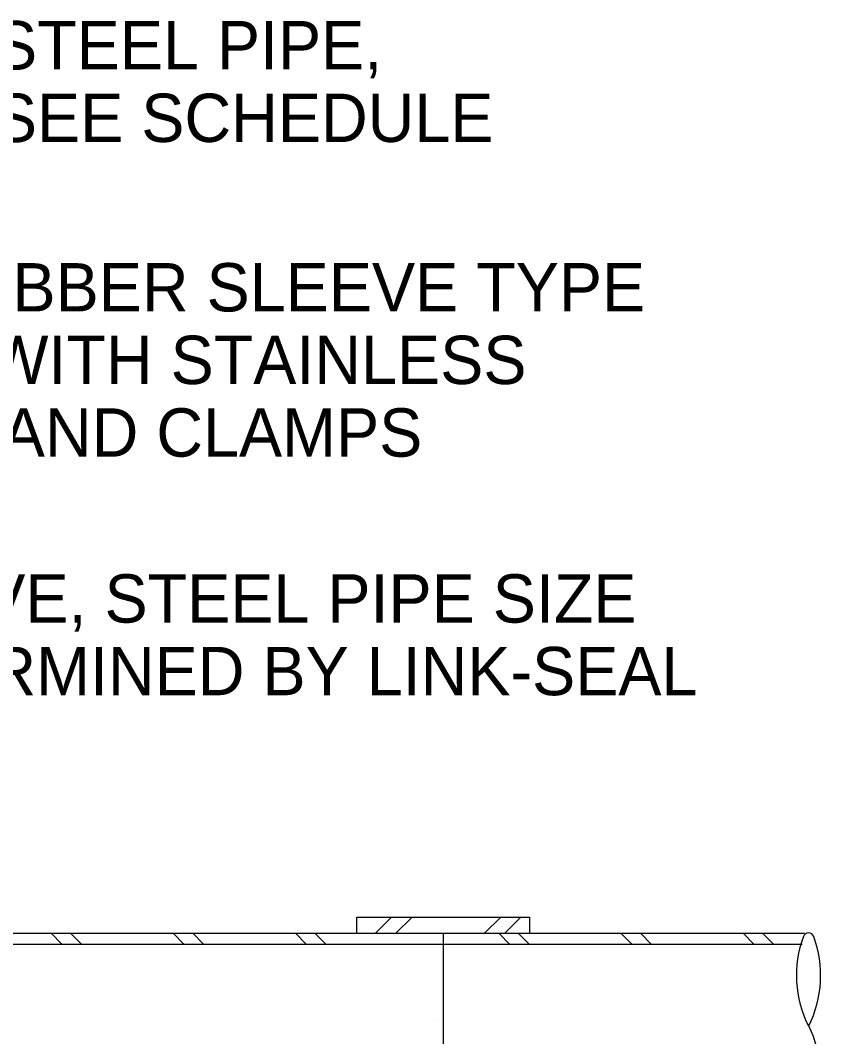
# Model space of a CAD drawing. Extents: x 22422.9 to 22498.9, y 22369.6 to 22415.
# Drawn here: x 22434.748 to 22437.837, y 22392.447 to 22396.373 of the extents above; entities that cross this region are included whole.
import ezdxf

# ---------------------------------------------------------------- set-up
doc = ezdxf.new("R2010")
doc.units = 0
for name, color, linetype in [('Level 1', 7, 'Continuous'), ('Level 2', 7, 'Continuous'), ('Level 4', 7, 'Continuous'), ('Level 8', 7, 'Continuous')]:
    doc.layers.add(name, color=color, linetype=linetype)

msp = doc.modelspace()

# ---------------------------------------------------------------- linework, layer by layer
at = {"layer": 'Level 1'}
for p, q in [((22436.3804, 22392.5676), (22436.3804, 22392.5676)), ((22436.3443, 22392.5084), (22436.3443, 22392.5084))]:
    msp.add_line(p, q, dxfattribs=at)
for centre, radius, start, end in [((22437.7898, 22392.8266), 0.0213, 20.1936, 159.8064), ((22438.1786, 22392.6836), 0.4356, 159.8064, 206.6071), ((22437.4009, 22392.6836), 0.4356, 333.3929, 20.1936), ((22437.4009, 22392.2934), 0.4356, 339.8081, 26.6071)]:
    msp.add_arc(centre, radius, start, end, dxfattribs=at)
at = {"layer": 'Level 2'}
for p, q in [((22436.0471, 22392.8467), (22436.0471, 22392.9092)), ((22436.0471, 22392.9092), (22436.7137, 22392.9092)), ((22436.7137, 22392.8467), (22436.7137, 22392.9092)), ((22431.1304, 22392.8467), (22437.7746, 22392.8467)), ((22436.3804, 22392.1279), (22436.3804, 22392.8467)), ((22431.1304, 22392.805), (22437.765, 22392.805))]:
    msp.add_line(p, q, dxfattribs=at)
at = {"layer": 'Level 8'}
for points in [[(22436.1804, 22392.9092), (22436.1179, 22392.8467)], [(22436.2601, 22392.9092), (22436.1976, 22392.8467)], [(22436.6023, 22392.9092), (22436.5398, 22392.8467)], [(22436.6799, 22392.9092), (22436.6174, 22392.8467)], [(22434.908, 22392.805), (22434.8663, 22392.8467)], [(22434.9834, 22392.805), (22434.9418, 22392.8467)], [(22435.3794, 22392.805), (22435.3378, 22392.8467)], [(22435.4548, 22392.805), (22435.4132, 22392.8467)], [(22435.8508, 22392.805), (22435.8092, 22392.8467)], [(22435.9262, 22392.805), (22435.8846, 22392.8467)], [(22436.6359, 22392.805), (22436.5943, 22392.8467)], [(22436.7114, 22392.805), (22436.6697, 22392.8467)], [(22437.1073, 22392.805), (22437.0657, 22392.8467)], [(22437.1828, 22392.805), (22437.1411, 22392.8467)], [(22437.5787, 22392.805), (22437.5371, 22392.8467)], [(22437.6542, 22392.805), (22437.6125, 22392.8467)]]:
    msp.add_lwpolyline(points, dxfattribs=at)

# ---------------------------------------------------------------- texts
at = {"layer": 'Level 4'}
for s, p in [('SLEEVE, STD. STEEL PIPE,', (22432.8983, 22396.1831)), ('FOR LENGTH, SEE SCHEDULE', (22432.8983, 22395.9027)), ('NEOPRENE RUBBER SLEEVE TYPE', (22432.8867, 22395.2482)), ('CASING SEAL WITH STAINLESS', (22432.8867, 22394.9678)), ('STEEL BANDS AND CLAMPS', (22432.8867, 22394.6874)), ('SLEEVE, STEEL PIPE SIZE', (22433.9627, 22394.0464)), ('DETERMINED BY LINK-SEAL', (22433.9627, 22393.766))]:
    msp.add_text(s, height=0.186667, dxfattribs=at).set_placement(p)

doc.saveas('drawing.dxf')
